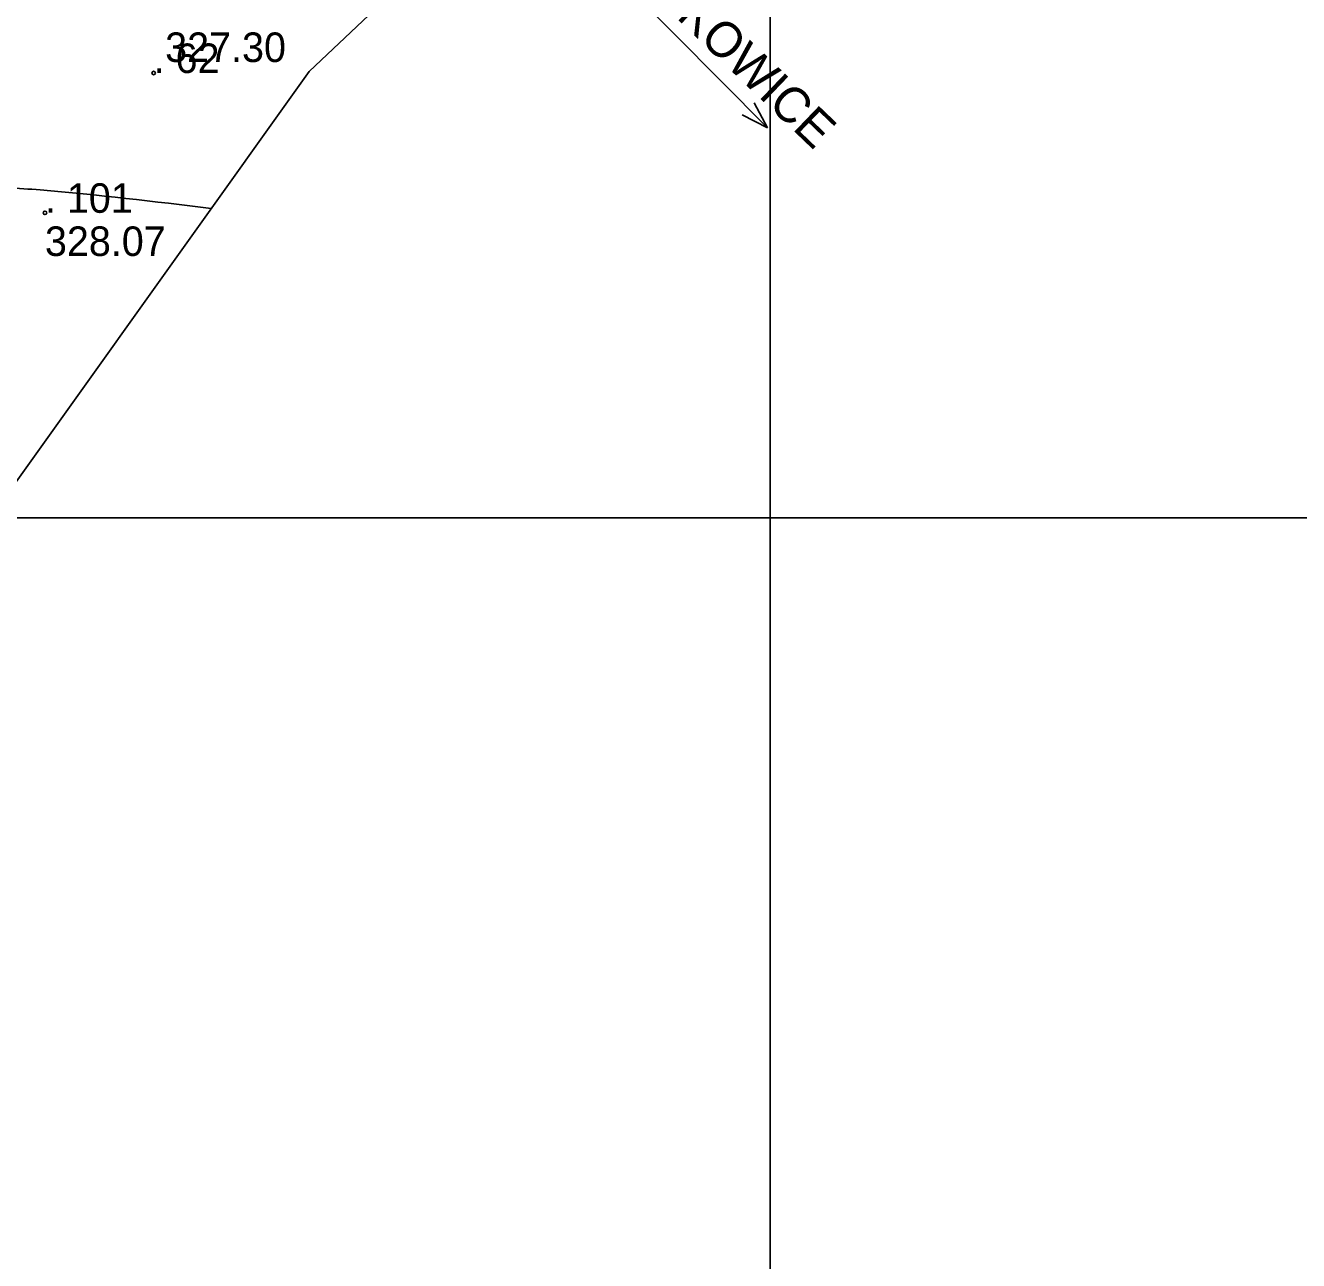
# Model space of a CAD drawing. Extents: x 4632591 to 4653165, y 5351032 to 5369868.
# Drawn here: x 4644762.2 to 4644826.8, y 5358462.3 to 5358525 of the extents above; entities that cross this region are included whole.
import ezdxf

# ---------------------------------------------------------------- set-up
doc = ezdxf.new("R2010")
doc.units = 0
for name, color, linetype in [('SDRPK_432', 7, 'Continuous'), ('Warstwa 40', 7, 'Continuous'), ('Warstwa 60', 7, 'Continuous'), ('Warstwa 62', 7, 'Continuous'), ('WUKPS_403', 7, 'Continuous'), ('WWRPH_811', 7, 'Continuous')]:
    doc.layers.add(name, color=color, linetype=linetype)

msp = doc.modelspace()

# ---------------------------------------------------------------- linework, layer by layer
at = {"layer": 'SDRPK_432'}
for q in [(4644799.186248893, 5358521.088252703), (4644798.587566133, 5358520.482996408)]:
    msp.add_line((4644799.8626311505, 5358519.8204980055), q, dxfattribs=at)
msp.add_lwpolyline([(4644799.8626311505, 5358519.8204980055), (4644788.077488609, 5358531.713830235)], dxfattribs=at)
at = {"layer": 'Warstwa 40'}
msp.add_lwpolyline([(4644810.829869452, 5358555.0318941), (4644734.3245207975, 5358627.5855483), (4644688.903956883, 5358576.341480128), (4644696.208771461, 5358541.053777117), (4644665.649831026, 5358513.078865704), (4644675.210413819, 5358482.874703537), (4644634.264162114, 5358446.154900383), (4644624.659923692, 5358448.078175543), (4644610.340877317, 5358444.40646842), (4644593.08287162, 5358445.769308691), (4644584.820738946, 5358446.421757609), (4644558.950406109, 5358331.354730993), (4644690.288366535, 5358293.195203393), (4644705.733104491, 5358386.519320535), (4644692.287170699, 5358404.571880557), (4644776.589601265, 5358522.671629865)], close=True, dxfattribs=at)
at = {"layer": 'Warstwa 60'}
for points in [[(4644000, 5358500), (4644000, 5359000), (4644800, 5359000), (4644800, 5358500)], [(4644800, 5358500), (4644800, 5359000), (4645600, 5359000), (4645600, 5358500)], [(4644000, 5358000), (4644000, 5358500), (4644800, 5358500), (4644800, 5358000)], [(4644800, 5358000), (4644800, 5358500), (4645600, 5358500), (4645600, 5358000)]]:
    msp.add_lwpolyline(points, close=True, dxfattribs=at)
at = {"layer": 'WUKPS_403'}
for centre in [(4644768.7, 5358522.600000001), (4644763.18, 5358515.5)]:
    msp.add_circle(centre, 0.09, dxfattribs=at)
at = {"layer": 'WWRPH_811'}
msp.add_spline([(4644771.62738981, 5358515.720039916), (4644762.939897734, 5358516.659724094), (4644759.588817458, 5358516.828865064), (4644756.238759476, 5358516.6693922), (4644752.889382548, 5358516.268575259), (4644749.54034543, 5358515.7136839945)], degree=3, dxfattribs=at)

# ---------------------------------------------------------------- texts
at = {"layer": 'SDRPK_432'}
msp.add_text('DOMINIKOWICE', height=1.7999999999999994, rotation=316.18830933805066, dxfattribs=at).set_placement((4644788.931847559, 5358531.42557358))
at = {"layer": 'Warstwa 62'}
for s, p in [('. 62', (4644768.7, 5358522.600000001)), ('. 101', (4644763.18, 5358515.5))]:
    msp.add_text(s, height=1.5, dxfattribs=at).set_placement(p)
at = {"layer": 'WUKPS_403'}
for s, p in [('327.30', (4644769.283096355, 5358523.159718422)), ('328.07', (4644763.18, 5358513.307837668))]:
    msp.add_text(s, height=1.5, dxfattribs=at).set_placement(p)

doc.saveas('drawing.dxf')
